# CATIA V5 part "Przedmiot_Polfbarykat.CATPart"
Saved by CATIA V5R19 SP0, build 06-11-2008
Part number: Part1
Bounding box of the stored display mesh (mm): x -100 to 100, y -100 to 100, z 0 to 55
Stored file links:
  D:\POBO\podręcznik\ProcesTechnologiczny\Frez-CD\Przedmiot_Polfbarykat.CATPart
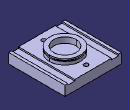
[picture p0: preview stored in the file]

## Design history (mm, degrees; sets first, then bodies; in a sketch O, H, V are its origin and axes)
Body1 "Przedmiot" (main body)
  Sketch1 on xy-plane, origin (0, 0, 0), H (1, 0, 0), V (0, 1, 0)
    line L1 (-100, 100) -> (100, 100)
    line L2 (100, 100) -> (100, -100)
    line L3 (100, -100) -> (-100, -100)
    line L4 (-100, -100) -> (-100, 100)
    length L1 = 200
    length L4 = 200
    distance H L1 = 100
    distance V L4 = 100
    horizontal: L1 H, L3 H
    vertical: L2 V, L4 V
  Pad1: profile Sketch1, direction (0, 0, 1), length 35
  Sketch2 on end face of Pad1, origin (0, 0, 35), H (1, 0, 0), V (0, 1, 0)
    circle A1 centre (0, 0) radius 40
    circle A2 centre (0, 0) radius 55
    radius A1 = 40
    radius A2 = 55
  Pad2: profile Sketch2, direction (0, 0, 1), length 20
  Sketch3 on end face of Pad1, origin (0, 0, 35), H (1, 0, 0), V (0, 1, 0)
    line L1 (65, 109.0671) -> (90, 109.0671)
    line L2 (90, 109.0671) -> (90, -110.9899)
    line L3 (90, -110.9899) -> (65, -110.9899)
    line L4 (65, -110.9899) -> (65, 109.0671)
    line L5 (-90, 104.385) -> (-65, 104.385)
    line L6 (-65, 104.385) -> (-65, -110.9899)
    line L7 (-65, -110.9899) -> (-90, -110.9899)
    line L8 (-90, -110.9899) -> (-90, 104.385)
    point P7 (-65, -110.9899)
    reference projected line E1 (100, -100) -> (100, 100) from edge [face of Pad1 from Sketch1.L2 | end face of Pad1]
    reference projected line E2 (-100, 100) -> (-100, -100) from edge [face of Pad1 from Sketch1.L4 | end face of Pad1]
    length L1 = 25
    length L5 = 25
    distance L2 E1 = 10
    distance L8 E2 = 10
    horizontal: L1 H, L3 H, L5 H, L7 H
    vertical: L2 V, L4 V, L6 V, L8 V
    coincidence: P7 L3
  Pocket1: profile Sketch3, direction (0, 0, -1), length 5
  Sketch4 on end face of Pad1, origin (0, 0, 35), H (1, 0, 0), V (0, 1, 0)
    circle A1 centre (0, 75) radius 7.5
    point P1 (0, 75)
    circle A2 centre (0, -75) radius 7.5
    point P2 (0, -75)
    reference projected line E1 (100, 100) -> (-100, 100) from edge [face of Pad1 from Sketch1.L1 | end face of Pad1]
    reference projected line E2 (-100, -100) -> (100, -100) from edge [face of Pad1 from Sketch1.L3 | end face of Pad1]
    radius A1 = 7.5
    radius A2 = 7.5
    distance P1 E1 = 25
    distance P2 E2 = 25
    coincidence: P1 V, P2 V
  Pocket2: profile Sketch4, direction (0, 0, -1), through (limit type 6)
  Sketch5 on yz-plane, origin (0, 0, 0), H (0, 1, 0), V (0, 0, 1)
    line L1 (-55, 50) -> (-51, 50)
    line L2 (-51, 50) -> (-51, 46)
    line L3 (-51, 46) -> (-55, 46)
    line L4 (-55, 46) -> (-55, 50)
    reference projected line E1 (-55, 55) -> (55, 55) from edge [face of Pad2 from Sketch2.A2 | end face of Pad2]
    reference projected line E2 through (0, 0) direction (0, 1) from axis of face of Pad2 from Sketch2.A2
    length L3 = 4
    length L4 = 4
    distance L1 E1 = 5
    distance L4 E2 = 55
    horizontal: L1 H, L3 H
    vertical: L2 V, L4 V
  Groove1: profile Sketch5, axis Sketch5.V, angle 360
Body2 "Polfabrykat"
  Sketch6 on xy-plane, origin (0, 0, 0), H (1, 0, 0), V (0, 1, 0)
    line L1 (-100, 100) -> (100, 100)
    line L2 (100, 100) -> (100, -100)
    line L3 (100, -100) -> (-100, -100)
    line L4 (-100, -100) -> (-100, 100)
    reference projected line E1 (-100, 100) -> (-100, -100) from edge [face of Pad1 from Sketch1.L4 | end face of Pad1]
    reference projected line E2 (100, 100) -> (-100, 100) from edge [face of Pad1 from Sketch1.L1 | end face of Pad1]
    length L2 = 200
    length L1 = 200
    distance L4 E1 = 0
    distance L1 E2 = 0
    horizontal: L1 H, L3 H
    vertical: L2 V, L4 V
  Pad3: profile Sketch6, direction (0, 0, 1), length 60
